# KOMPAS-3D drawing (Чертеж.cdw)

Referenced files in C:\Program Files\ASCON\KOMPAS-3D V10\Libs\: PGS.LFR|Вентили|Вентиль 01, PGS.LFR
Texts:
  Схема автоматизації
  Виталий
  Samsung Electronics
  Текст на чертеже
  Размерные надписи
  Шероховатость
  Линия-выноска #1
  Линия-выноска #2
  Линия-выноска #3
  Отклонения формы и база
  Заголовок таблицы
  Ячейка таблицы
  Стрелка вида
  Обозначение изменения
  Фигурная скобка
  Номер узла
  Марка координационной оси
  VRCB
  Выносная надпись
  Обозначение узла
  Марка/позиционное обозначение с линией-выноской
  Марка/позиционное обозначение на линии
  Марка/позиционное обозначение без линии-выноски
  Вентили|Вентиль 01
  Вентиль запорный
  проходной
  HL1
  PDA
  PDC
  FFC
  FFY
  FFc
  PDS
  PD1
  PDT
  LIK
  Прилади
  по місцю
  Прилади на щиті
  LIR
  HL5
  HL6
  HL4
  HL3
  HL2
  FFR
  TRC
  не менше 1.2м
  не більше 0.02мПа
  не більше 0.03мПа
  з електричної
  схеми
  стружка
  пара
  із збірника
  барометричної води
  із збірника жомопресової
  води
  жом на преси
  сік на дефектосатурацію
  Дифузійний сік
  Барометрична вода
  Жомопресова вода
  Жом
  Пара
  Гах В.П.
  НУХТ ЗМ-6-3
Dimensions and other numbers on the sheet: 03-3604.ДП.СА; 7; 1; 2; 3; 4; 5; 6; 8; 9; 10; 11; 12; 13; 15; 14; 18; 19; 20; 21; 22; 23; 24; 16; 17; 25; 26; 27; 28; 29; 30; 31; 32; 33; 34; 11и; 10б; 10д; 10е; 10в; 10г; 10ж; 11к; 12б; 13в; 13б; 13г; 14б; 14г; 14в; 15б; 15в; 16а; 16б; 16в; 16д; 16г; 13д; 17г; 17д; 17б; 17з; 17а; 12а; 10а; 78+1 С; 71+1 С; 25+5%; 75+5%; 16+0.3м; 2.2+0.3м; 2шт.; 13а; 11а; 11в; 11б; 11г; 15г; 10к; 14а; 11д; 11е; 11ж; 15а; 03-3604.ДП.СА-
